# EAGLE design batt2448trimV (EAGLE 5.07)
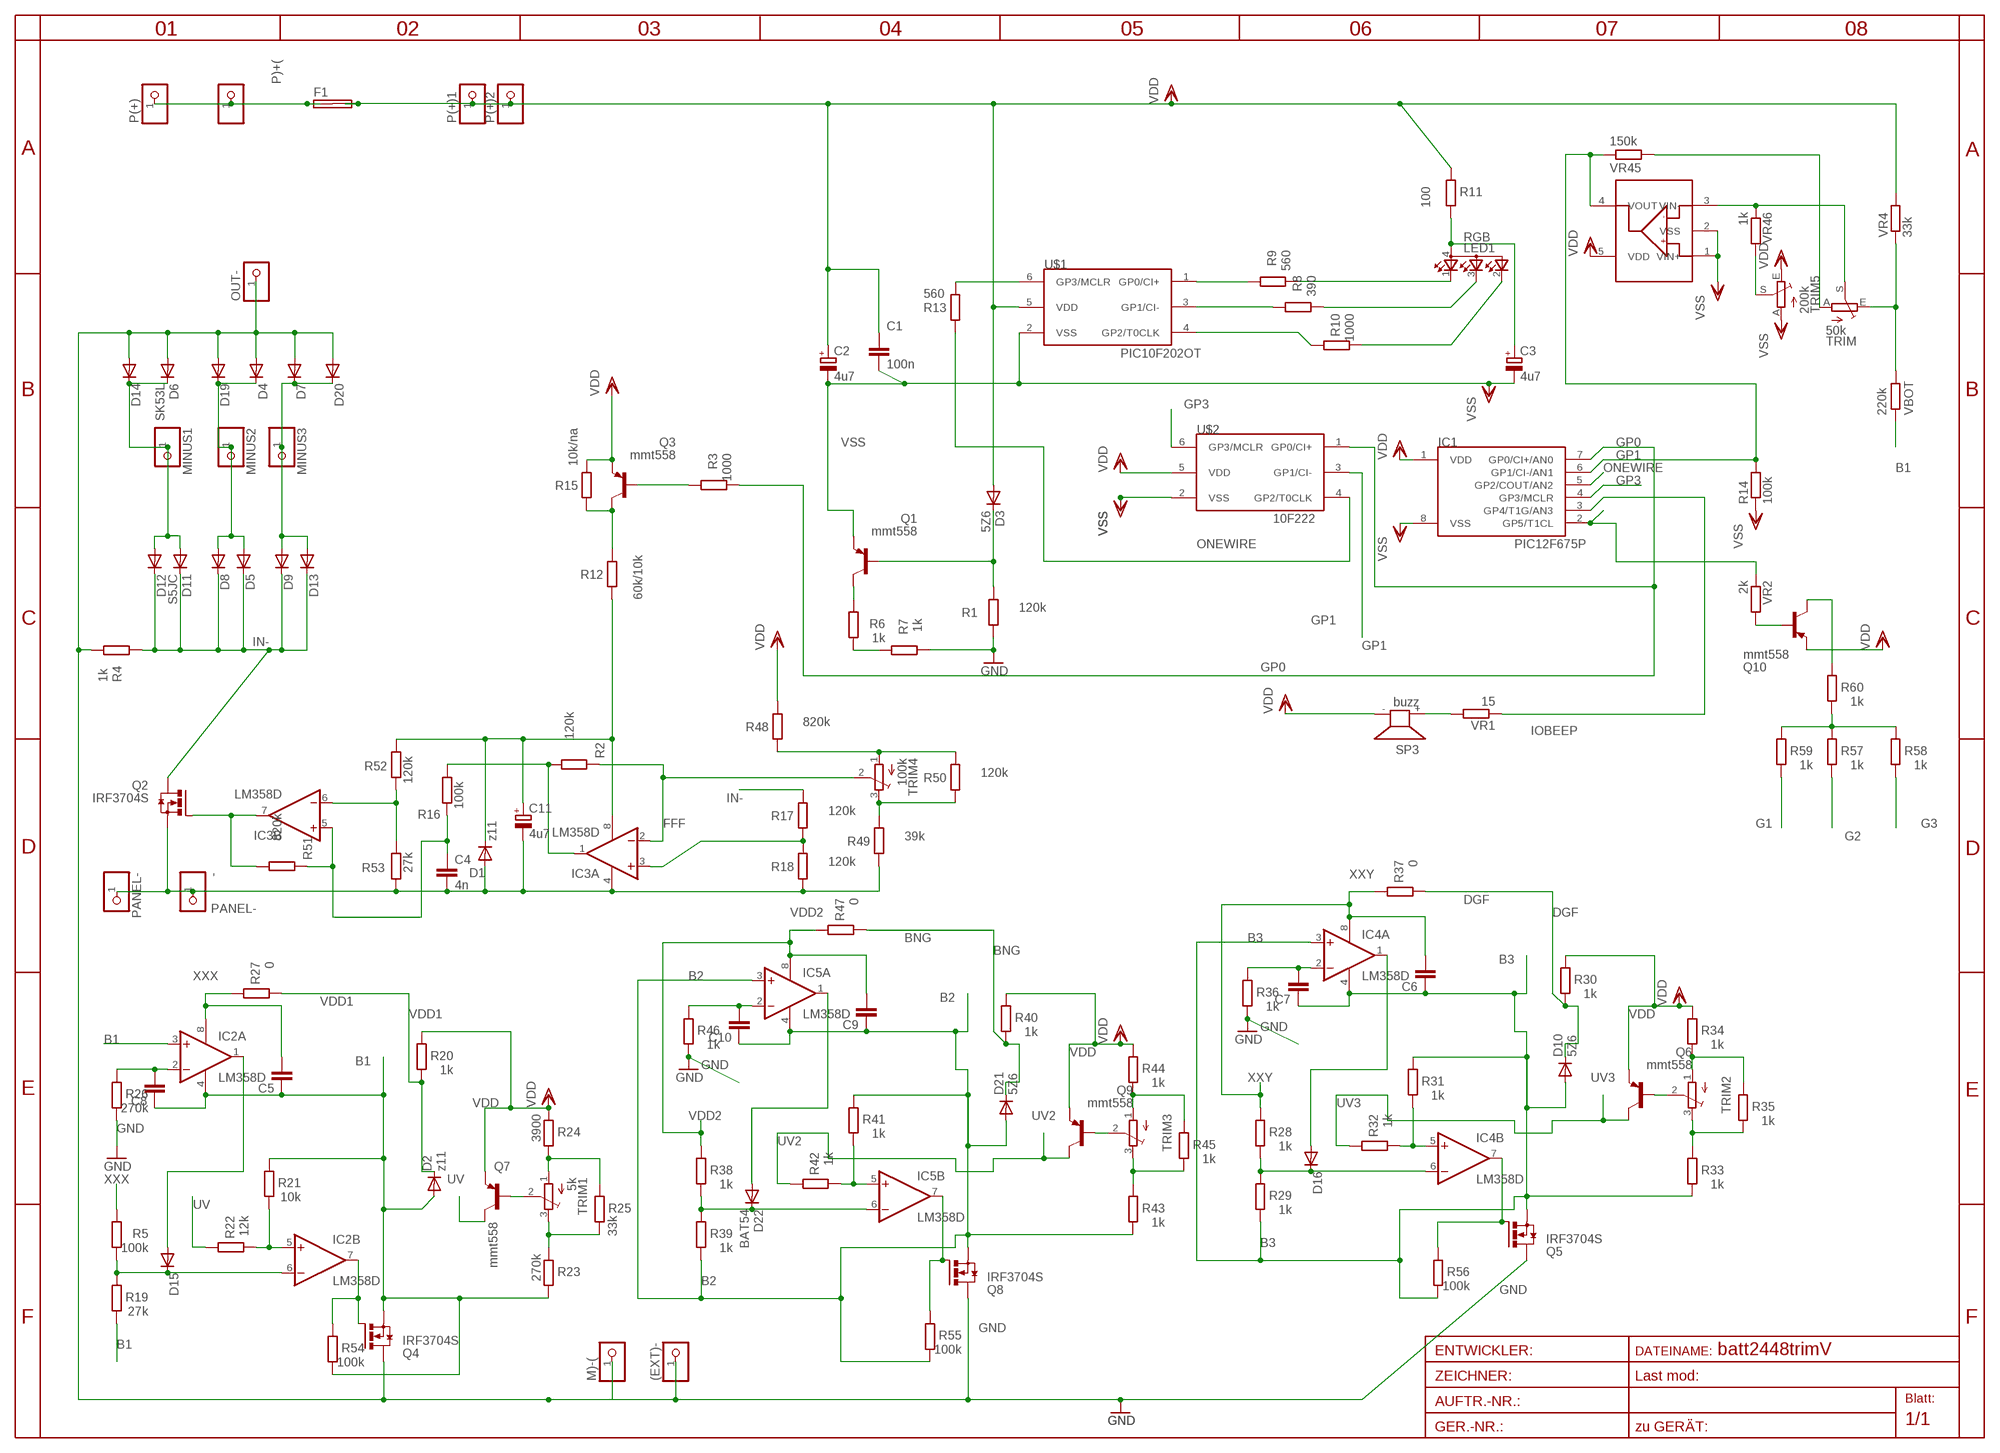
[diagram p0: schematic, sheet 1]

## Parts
(EXT)-  PINHD-1X11MM6  [1X1MM8]
-  PINHD-1X11MM6  [1X1MM8]
C1  100n  C-EUC1206  [C1206]
C2  4u7  CPOL-EUSMCA  [SMC_A]
C3  4u7  CPOL-EUSMCA  [SMC_A]
C4  4n  C-EUC0805  [C0805]
C5  C-EUC1206  [C1206]
C6  C-EUC1206  [C1206]
C7  C-EUC0805  [C0805]
C8  C-EUC0805  [C0805]
C9  C-EUC1206  [C1206]
C10  C-EUC0805  [C0805]
C11  4u7  CPOL-EUSANYO_SMD_B6  [SANYO-OSCON_SMD_B6]
D1  z11  DIODE-MINIMELF  [MINIMELF]
D2  z11  DIODE-MINIMELF  [MINIMELF]
D3  5Z6  DIODE-MINIMELF  [MINIMELF]
D4  DIODE-SMC  [SMC]
D5  DIODE-SMC  [SMC]
D6  SK53L  DIODE-SMC  [SMC]
D7  DIODE-SMC  [SMC]
D8  DIODE-SMC  [SMC]
D9  DIODE-SMC  [SMC]
D10  5Z6  DIODE-MINIMELF  [MINIMELF]
D11  S5JC  DIODE-SMC  [SMC]
D12  DIODE-SMC  [SMC]
D13  DIODE-SMC  [SMC]
D14  DIODE-SMC  [SMC]
D15  DIODE-MINIMELF  [MINIMELF]
D16  DIODE-MINIMELF  [MINIMELF]
D19  DIODE-SMC  [SMC]
D20  DIODE-SMC  [SMC]
D21  5Z6  DIODE-MINIMELF  [MINIMELF]
D22  BAT54  DIODE-MINIMELF  [MINIMELF]
F1  SHK20L7MM5  [7MM5]
IC1  PIC12F675P  [DIL8]
IC2  LM358D  [SO08]
IC3  LM358D  [SO08]
IC4  LM358D  [SO08]
IC5  LM358D  [SO08]
IC6  MCP6001U  [SOT23-5L]
LED1  RGB  GM1WA55311A  [FULL3528]
M)-(  PINHD-1X11MM6  [1X1MM8]
MINUS1  PINHD-1X12MM3  [1X2MM3]
MINUS2  PINHD-1X12MM3  [1X2MM3]
MINUS3  PINHD-1X12MM3  [1X2MM3]
OUT-  PINHD-1X12MM3  [1X2MM3]
P(+)  PINHD-1X12MM3  [1X2MM3]
P(+)1  PINHD-1X12MM3  [1X2MM3]
P(+)2  PINHD-1X13MM2  [1X3MM2]
P)+(  PINHD-1X11X0.4  [1X01]
PANEL-  PINHD-1X12MM3  [1X2MM3]
Q1  mmt558  BC857ALT1SMD  [SOT23-BEC]
Q2  IRF3704S  [D2PACK]
Q3  mmt558  BC857ALT1SMD  [SOT23-BEC]
Q4  IRF3704S  [D2PACK]
Q5  IRF3704S  [D2PACK]
Q6  mmt558  BC857ALT1SMD  [SOT23-BEC]
Q7  mmt558  BC857ALT1SMD  [SOT23-BEC]
Q8  IRF3704S  [D2PACK]
Q9  mmt558  BC857ALT1SMD  [SOT23-BEC]
Q10  mmt558  BC857ALT1SMD  [SOT23-BEC]
R1  120k  R-EU_R1206  [R1206]
R2  120k  R-EU_R0805  [R0805]
R3  1000  R-EU_R0805  [R0805]
R4  1k  R-EU_0207/25  [0207/25]
R5  100k  R-EU_R1206  [R1206]
R6  1k  R-EU_R1206  [R1206]
R7  1k  R-EU_R1206  [R1206]
R8  390  R-EU_R0805  [R0805]
R9  560  R-EU_R0805  [R0805]
R10  1000  R-EU_R0805  [R0805]
R11  100  R-EU_R1206  [R1206]
R12  60k/10k  R-EU_R1206  [R1206]
R13  560  R-EU_R0805  [R0805]
R14  100k  R-EU_R1206  [R1206]
R15  10k/na  R-EU_R0805  [R0805]
R16  100k  R-EU_R0805  [R0805]
R17  120k  R-EU_R0805  [R0805]
R18  120k  R-EU_R0805  [R0805]
R19  27k  R-EU_R0805  [R0805]
R20  1k  R-EU_R1206  [R1206]
R21  10k  R-EU_R0805  [R0805]
R22  12k  R-EU_R1206  [R1206]
R23  270k  R-EU_R0805  [R0805]
R24  3900  R-EU_R0805  [R0805]
R25  33k  R-EU_R0805  [R0805]
R26  270k  R-EU_R1206  [R1206]
R27  0  R-EU_R1203  [R1203]
R28  1k  R-EU_R1206  [R1206]
R29  1k  R-EU_R0805  [R0805]
R30  1k  R-EU_R1206  [R1206]
R31  1k  R-EU_R0805  [R0805]
R32  1k  R-EU_R1206  [R1206]
R33  1k  R-EU_R0805  [R0805]
R34  1k  R-EU_R0805  [R0805]
R35  1k  R-EU_R0805  [R0805]
R36  1k  R-EU_R1206  [R1206]
R37  0  R-EU_R1203  [R1203]
R38  1k  R-EU_R1206  [R1206]
R39  1k  R-EU_R0805  [R0805]
R40  1k  R-EU_R1206  [R1206]
R41  1k  R-EU_R0805  [R0805]
R42  1k  R-EU_R1206  [R1206]
R43  1k  R-EU_R0805  [R0805]
R44  1k  R-EU_R0805  [R0805]
R45  1k  R-EU_R0805  [R0805]
R46  1k  R-EU_R1206  [R1206]
R47  0  R-EU_R1203  [R1203]
R48  820k  R-EU_R0805  [R0805]
R49  39k  R-EU_R1206  [R1206]
R50  120k  R-EU_R0805  [R0805]
R51  820k  R-EU_R0805  [R0805]
R52  120k  R-EU_R1206  [R1206]
R53  27k  R-EU_R1206  [R1206]
R54  100k  R-EU_R0805  [R0805]
R55  100k  R-EU_R0805  [R0805]
R56  100k  R-EU_R0805  [R0805]
R57  1k  R-EU_0207-17MM5  [0207/17MM5]
R58  1k  R-EU_0207-17MM5  [0207/17MM5]
R59  1k  R-EU_0207/10  [0207/10]
R60  1k  R-EU_R0805  [R0805]
SP3  buzz  KSS12017MM  [KSS1202]
TRIM  50k  TRIM_EU-S64W  [S64W]
TRIM1  5k  TRIM_EU-3223G  [3223G]
TRIM2  TRIM_EU-3223G  [3223G]
TRIM3  TRIM_EU-3223G  [3223G]
TRIM4  100k  TRIM_EU-3223G  [3223G]
TRIM5  200k  TRIM_EU-S64W  [S64W]
U$1  PIC10F202OT  [SOT23-6]
U$2  10F222  PIC10F204OT  [SOT23-6]
VBOT  220k  R-EU_R0805  [R0805]
VR1  15  R-EU_R0805  [R0805]
VR2  2k  R-EU_R0805  [R0805]
VR4  33k  R-EU_R1206  [R1206]
VR45  150k  R-EU_R0805  [R0805]
VR46  1k  R-EU_R0805  [R0805]

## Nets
A: C3.+ LED1.4(A) R11.1
B: LED1.3(CBLUE) R8.1
B1: C5.1 C8.1 D2.A D6.C D11.A D12.A D14.C IC2.3(A:+IN) IC2.4(P:V-) MINUS1.1 Q4.3(S) R19.1 R21.2 R23.1 R54.1 VBOT.1
B2: C9.1 C10.1 D7.C D9.A D13.A D20.C D21.A IC5.3(A:+IN) IC5.4(P:V-) MINUS3.1 Q8.3(S) R39.1 R41.2 R43.1 R55.1
B3: C6.1 C7.1 D4.C D5.A D8.A D10.A D19.C IC4.3(A:+IN) IC4.4(P:V-) MINUS2.1 Q5.3(S) R29.1 R31.2 R33.1 R56.1
BNG: D21.C R40.1 R47.1
BUZZ+: SP3.+ VR1.2
DGF: D10.C R30.1 R37.1
DIGOUT: R57.2 R58.2 R59.2 R60.1
FFF: IC3.2(A:-IN) R2.2 TRIM4.2(S)
G: LED1.2(CGREEN) R10.1
G1: IC2.7(B:OUT) Q4.1(G) R54.2 R59.1
G2: IC5.7(B:OUT) Q8.1(G) R55.2 R57.1
G3: IC4.7(B:OUT) Q5.1(G) R56.2 R58.1
GND: (EXT)-.1 D4.A D6.A D7.A D14.A D19.A D20.A M)-(.1 OUT-.1 Q4.2(D) Q5.2(D) Q8.2(D) R1.2 R4.1 R7.1 R26.1 R36.1 R46.1
GP0: IC1.7(GP0/CI+/AN0) R3.1 U$2.1(GP0/CI+)
GP0C: R9.2 U$1.1(GP0/CI+)
GP1: IC1.6(GP1/CI-/AN1) IC6.4(VOUT) R14.2 U$2.3(GP1/CI-) VR45.1
GP1C: R8.2 U$1.3(GP1/CI-)
GP2C: R10.2 U$1.4(GP2/T0CLK)
GP3: IC1.4(GP3/MCLR) U$2.6(GP3/MCLR)
GP3_2: R13.1 U$1.6(GP3/MCLR)
IN+: F1.1A F1.1B P(+).1 P)+(.1
IN-: D5.C D8.C D9.C D11.C D12.C D13.C Q2.2(D) R4.2 R17.1
IOBEEP: IC1.3(GP4/T1G/AN3) VR1.1
N$1: D15.C IC2.6(B:-IN) R5.1 R19.2
N$2: D3.C Q1.B R1.1
N$4: C11.+ D1.C IC3.8(P:V+) R12.2 R52.1
N$5: TRIM.E VBOT.2 VR4.1
N$6: Q1.C R6.2
N$7: TRIM5.S VR46.2
N$8: Q3.B R3.2
N$9: Q10.B VR2.2
N$10: IC2.5(B:+IN) R21.1 R22.1
N$11: Q3.C R12.1 R15.2
N$12: TRIM.A VR45.2
N$13: IC3.1(A:OUT) R2.1 R16.1
N$14: IC6.3(VIN-) TRIM.S VR46.1
N$16: IC3.3(A:+IN)
N$17: D15.A IC2.1(A:OUT)
N$18: R6.1 R7.2
N$19: R17.2 R18.1
N$20: C8.2 IC2.2(A:-IN) R26.2
N$21: Q7.B TRIM1.2(S)
N$22: R24.1 R25.2 TRIM1.1(A)
N$23: R23.2 R25.1 TRIM1.3(E)
N$24: IC3.6(B:-IN) R52.2 R53.1
N$25: D16.C IC4.6(B:-IN) R28.1 R29.2
N$26: IC4.5(B:+IN) R31.1 R32.1
N$27: Q6.B TRIM2.2(S)
N$30: R34.1 R35.2 TRIM2.1(A)
N$31: R33.2 R35.1 TRIM2.3(E)
N$32: D16.A IC4.1(A:OUT)
N$33: C7.2 IC4.2(A:-IN) R36.2
N$34: Q10.C R60.2
N$35: D22.C IC5.6(B:-IN) R38.1 R39.2
N$36: IC5.5(B:+IN) R41.1 R42.1
N$37: Q9.B TRIM3.2(S)
N$38: IC1.2(GP5/T1CL) VR2.1
N$39: R44.1 R45.2 TRIM3.1(A)
N$40: R43.2 R45.1 TRIM3.3(E)
N$41: D22.A IC5.1(A:OUT)
N$42: C10.2 IC5.2(A:-IN) R46.2
N$43: R49.1 R50.2 TRIM4.3(E)
N$45: R48.2 R50.1 TRIM4.1(A)
N$46: C4.1 IC3.5(B:+IN) R16.2 R51.2
N$47: IC3.7(B:OUT) Q2.1(G) R51.1
ONEWIRE: IC1.5(GP2/COUT/AN2) R13.2 U$2.4(GP2/T0CLK)
PANEL-: -.1 C4.2 C11.- D1.A IC3.4(P:V-) PANEL-.1 Q2.3(S) R18.2 R49.2 R53.2
R: LED1.1(CRED) R9.1
UV: Q7.C R22.2
UV2: Q9.C R42.2
UV3: Q6.C R32.2
VDD: C1.1 C2.+ D3.A F1.2A F1.2B IC1.1(VDD) IC6.5(VDD) P(+)1.1 P(+)2.1 Q3.E Q6.E Q7.E Q9.E Q10.E R11.2 R15.1 R20.2 R24.2 R30.2 R34.2 R40.2 R44.2 R48.1 SP3.- TRIM5.E U$1.5(VDD) U$2.5(VDD) VR4.2
VDD1: D2.C R20.1 R27.1
VDD2: C9.2 IC5.8(P:V+) R38.2 R47.2
VSS: C1.2 C2.- C3.- IC1.8(VSS) IC6.1(VIN+) IC6.2(VSS) Q1.E R14.1 TRIM5.A U$1.2(VSS) U$2.2(VSS)
XXX: C5.2 IC2.8(P:V+) R5.2 R27.2
XXY: C6.2 IC4.8(P:V+) R28.2 R37.2

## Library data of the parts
(EXT)- - M)-( MINUS1-MINUS3 OUT- P(+) P(+)1 P(+)2 P)+( PANEL- = pinhead:PINHD-1X1: PIN HEADER
C1 C4-C10 = rcl:C-EU: CAPACITOR, European symbol
C2 C3 C11 = rcl:CPOL-EU: POLARIZED CAPACITOR, European symbol
D1-D16 D19-D22 = diode:DIODE-: DIODE
F1 = fuse:SHK20L: FUSE HOLDER 5 x 20 mm, SH contact, SHH1 Schukat, E1073 Buerklin
IC1 = microchip-3:PIC12F6*: uPC nW 1k Program Flash memory 2x Timer Comparator 10b A/D converter/ 4xIN
IC2-IC5 = linear:LM358: OP AMP also LM158; LM258; LM2904 Source: http://cache.national.com/ds/LM/LM158.pdf
IC6 = microchip-3:MCP6001U
LED1 = led:GM1WA55311A: Chip LED RGB Source: http://document.sharpsma.com/files/GM1WA55311A_SS.pdf
Q1 Q3 Q6 Q7 Q9 Q10 = transistor-pnp:BC857*: PNP Transistror
Q2 Q4 Q5 Q8 = transistor-power:IRF3704: SMPS MOSFET HEXFET® Power MOSFET Source: http://www.irf.com/product-info/datasheets/data/irf3704.pdf
R1-R13 R15-R21 R23-R26 R28-R36 R38-R46 R48-R60 VBOT VR1 VR2 VR4 VR45 VR46 = rcl-2:R-EU_: RESISTOR, European symbol
R14 R22 R27 R37 R47 = rcl:R-EU_: RESISTOR, European symbol
SP3 = buzzer:KSS1201: SPEAKER
TRIM TRIM1-TRIM5 = pot:TRIM_EU-: POTENTIOMETER
U$1 U$2 = microchip-3:PIC10F2*: uPC nW 0,25/0,5k Program Flash memory Comparator

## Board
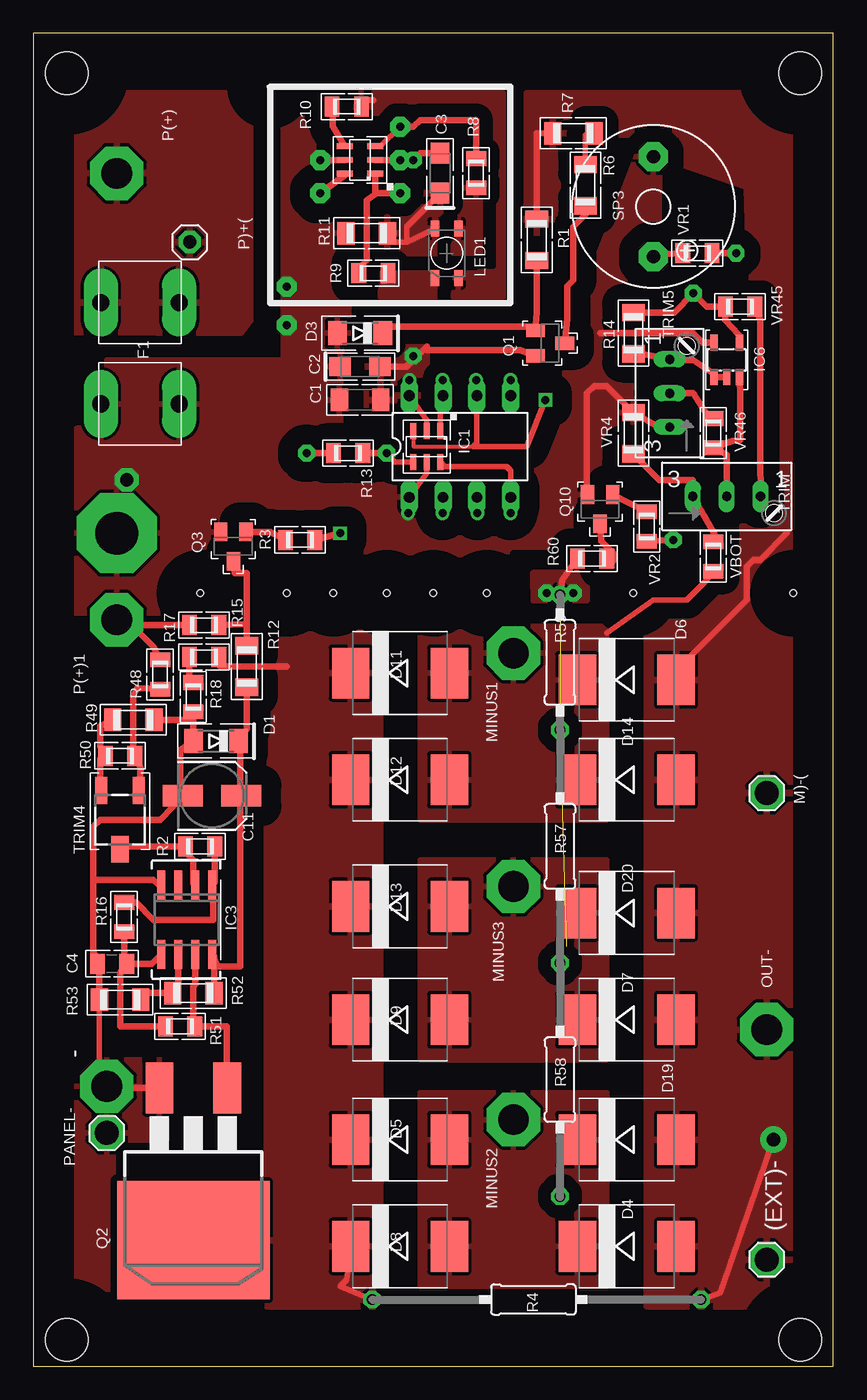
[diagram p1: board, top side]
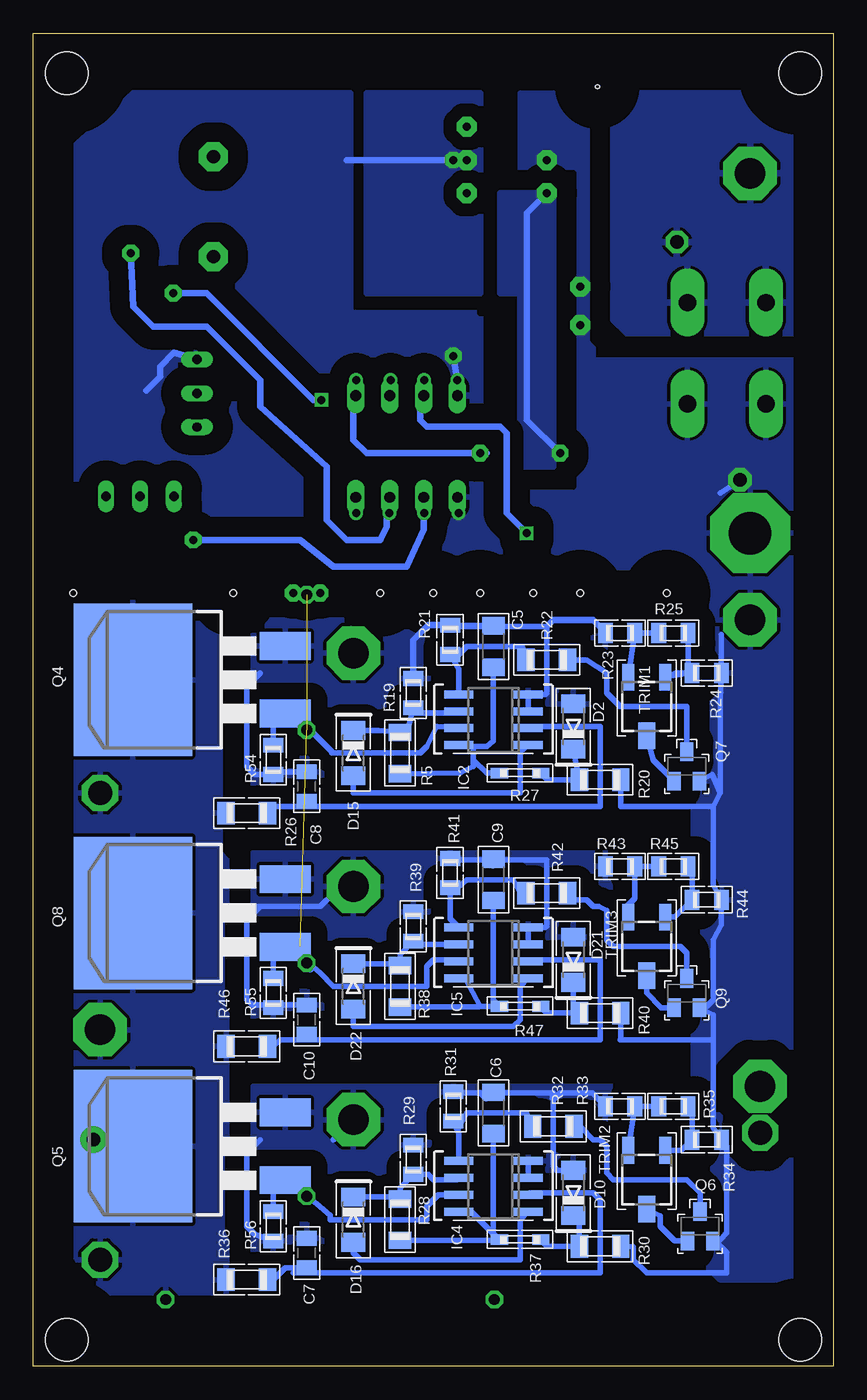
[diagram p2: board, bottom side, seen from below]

Size 60 x 100 mm. Coordinates in mm from the lower left corner, seen from the top.
Outline: 60,0 60,100 0,100 0,0 60,0
Copper layers (1*16): Top 0.035mm / dielectric 1.5mm / Bottom 0.035mm
Design rules "default *": minimum track width 8mil, minimum drill 0.3mm, track to track 8mil, track to pad 8mil, pad to pad 8mil, via to via 8mil, smd to smd 8mil, copper to edge 3mm, drill to drill 2mil, minimum pad ring 10mil, minimum via ring 8mil, stop-mask expansion 4mil, vias tented up to drill 0mil, thermal gap 10mil
Holes 3.2 mm at 2.5,2 57.5,2 2.5,97 57.5,97
Holes 0.5 mm at 34,58 30,58 26.5,58 22.5,58 45,58 57,58 19,58 12.5,58
Holes 0.3 mm at 17.7,96

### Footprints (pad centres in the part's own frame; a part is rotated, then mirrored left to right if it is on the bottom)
1X1MM8 = drill 1.8 pad 2.54 octagon: 1 0,0
C1206 = smd 1.3 x 1.7: 1 -1.55,0; 2 1.55,0
SMC_A = smd 1.6 x 1.4: + -1.5,0; - 1.5,0
C0805 = smd 1.1 x 1.5: 1 -1.1,0; 2 1.1,0
SANYO-OSCON_SMD_B6 = smd 3 x 1.6: + 2.2,0; - -2.2,0
MINIMELF = smd 1.4 x 1.8: A 1.7,0; C -1.7,0
SMC = smd 2.8 x 3.8: A 3.7,0; C -3.7,0
7MM5 = drill 1.3 pad 2.54 long: 1A -3.8,2.94; 1B -3.8,-2.94; 2A 3.8,2.94; 2B 3.8,-2.94
DIL8 = drill 0.813 long: 1 -3.81,-3.81; 2 -1.27,-3.81; 3 1.27,-3.81; 4 3.81,-3.81; 5 3.81,3.81; 6 1.27,3.81; 7 -1.27,3.81; 8 -3.81,3.81
SO08 = smd 0.6 x 2.2: 1 -1.905,-2.6; 2 -0.635,-2.6; 3 0.635,-2.6; 4 1.905,-2.6; 5 1.905,2.6; 6 0.635,2.6; 7 -0.635,2.6; 8 -1.905,2.6
SOT23-5L = smd 0.55 x 1.2: 1 -0.95,-1.3; 2 0,-1.3; 3 0.95,-1.3; 4 0.95,1.3; 5 -0.95,1.3
FULL3528 = smd 0.65 x 1.2: 1 0.875,1.85; 2 -0.875,1.85; 3 -0.875,-1.85; 4 0.875,-1.85
1X2MM3 = drill 2.3 pad 4 octagon: 1 0,0
1X3MM2 = drill 3.2 pad 6 octagon: 1 0,0
1X01 = drill 1 pad 1.676 octagon: 1 0,0
SOT23-BEC = smd 1 x 1.4: B -0.95,-1.1; C 0,1.1; E 0.95,-1.1
D2PACK = smd 2.083 x 3.81: 1 -2.54,-8.89; 3 2.54,-8.89 | smd 11.43 x 8.89: 2 0,2.54
R1206 = smd 1.3 x 1.7: 1 -1.55,0; 2 1.55,0
R0805 = smd 1.1 x 1.5: 1 -1.1,0; 2 1.1,0
0207/25 = drill 0.813 octagon: 1 -12.58,0; 2 12.08,0
R1203 = smd 1.3 x 0.8: 1 -1.55,0; 2 1.55,0
0207/17MM5 = drill 0.813 octagon: 1 -8.75,0; 2 8.75,0
0207/10 = drill 0.813 octagon: 1 -5.08,0; 2 5.08,0
KSS1202 = drill 1 pad 2.159 octagon: + 3.75,0; - -3.75,0
S64W = drill 0.7 long: A 2.54,1.27; E -2.54,1.27; S 0,1.27
3223G = smd 2 x 0.9: 1 -2.2,1.4; 3 -2.2,-1.4 | smd 2 x 1.3: 2 2.2,0
SOT23-6 = smd 0.45 x 1.2: 1 -1.016,-1.15; 2 0,-1.15; 3 1.016,-1.15; 4 1.016,1.15; 5 0,1.15; 6 -1.016,1.15

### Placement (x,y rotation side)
(EXT)-  55,8 90 top
-  5.5,17.5 90 top
C1  24.5,72.5 0 top
C2  24.5,75 0 top
C3  30.5,89.5 90 top
C4  5.9,30.2 180 top
C5  25.5,54 270 bottom
C6  25.5,19 270 bottom
C7  39.5,8.5 270 bottom
C8  39.5,43.5 270 bottom
C9  25.5,36.5 270 bottom
C10  39.5,26 270 bottom
C11  13.4,42.8 0 top
D1  13.7,46.9 180 top
D2  19.5,48 90 bottom
D3  24.5,77.5 180 top
D4  44.5,9 0 top
D5  27.5,17 0 top
D6  44.5,51.5 0 top
D7  44.5,26 0 top
D8  27.5,9 0 top
D9  27.5,26 0 top
D10  19.5,13 90 bottom
D11  27.5,52 0 top
D12  27.5,44 0 top
D13  27.5,34.5 0 top
D14  44.5,44 0 top
D15  36,46 270 bottom
D16  36,11 270 bottom
D19  44.5,17 0 top
D20  44.5,34 0 top
D21  19.5,30.5 90 bottom
D22  36,28.5 270 bottom
F1  8,76 270 top
IC1  32,69 0 top
IC2  25.5,48.5 90 bottom
IC3  11.5,33.5 180 top
IC4  25.5,13.5 90 bottom
IC5  25.5,31 90 bottom
IC6  52,75.5 0 top
LED1  31,83.5 180 top
M)-(  55,43 90 top
MINUS1  36,53.5 270 top
MINUS2  36,18.5 270 top
MINUS3  36,36 270 top
OUT-  55,25.25 270 top
P(+)  6.25,89.5 90 top
P(+)1  6.25,56 90 top
P(+)2  6.25,62.5 90 top
P)+(  11.73,84.34 90 top
PANEL-  5.5,21 270 top
Q1  38.75,76.75 270 top
Q2  12,12 180 top
Q3  15,61.5 180 top
Q4  50,51.5 90 bottom
Q5  50,16.5 90 bottom
Q6  10,10.5 0 bottom
Q7  11,45 0 bottom
Q8  50,34 90 bottom
Q9  11,28 0 bottom
Q10  42.5,64.3 180 top
R1  37.75,84.5 90 top
R2  12.5,39 180 top
R3  20,62 180 top
R4  37.5,5 180 top
R5  32.5,46 270 bottom
R6  41.4,88.6 270 top
R7  40.5,92.5 0 top
R8  33.2,89.5 90 top
R9  25.5,82 180 top
R10  23.5,94.5 180 top
R11  25,85 180 top
R12  16,52.5 270 top
R13  23.6,68.5 0 top
R14  45,77.5 90 top
R15  12.8,55.6 0 top
R16  6.8,33.7 270 top
R17  12.8,53.2 180 top
R18  12,50.2 270 top
R19  31.5,50.5 270 bottom
R20  17.5,44 0 bottom
R21  28.75,54.5 90 bottom
R22  21.5,53 0 bottom
R23  16,55 0 bottom
R24  9.5,52 0 bottom
R25  12,55 0 bottom
R26  44,41.5 0 bottom
R27  23.5,44.5 180 bottom
R28  32.5,11 270 bottom
R29  31.5,15.5 270 bottom
R30  17.5,9 0 bottom
R31  28.5,19.5 90 bottom
R32  21,18 0 bottom
R33  16,19.5 0 bottom
R34  9.5,17 0 bottom
R35  12,19.5 0 bottom
R36  44,6.5 0 bottom
R37  23.5,9.5 180 bottom
R38  32.5,28.5 270 bottom
R39  31.5,33 270 bottom
R40  17.5,26.5 0 bottom
R41  28.75,37 90 bottom
R42  21.5,35.5 0 bottom
R43  16,37.5 0 bottom
R44  9.5,35 0 bottom
R45  12,37.5 0 bottom
R46  44,24 0 bottom
R47  23.5,27 180 bottom
R48  9.5,51.9 270 top
R49  7.5,48.5 0 top
R50  6.5,45.8 180 top
R51  11,25.5 180 top
R52  12,28 180 top
R53  6.5,27.5 180 top
R54  42,45.5 90 bottom
R55  42,28 90 bottom
R56  42,10.5 90 bottom
R57  39.5,39 90 top
R58  39.5,21.5 90 top
R59  39.5,52.8 90 top
R60  41.9,60.6 0 top
SP3  46.5,87 270 top
TRIM  52,64 0 top
TRIM1  14,49.5 270 bottom
TRIM2  14,14 270 bottom
TRIM3  14,31.5 270 bottom
TRIM4  6.5,41 270 top
TRIM5  49,73 90 top
U$1  24.5,90.5 90 top
U$2  29.5,69 180 top
VBOT  51,60.75 90 top
VR1  49.8,83.5 180 top
VR2  46,63 90 top
VR4  45,70 90 top
VR45  53,79.5 0 top
VR46  51,70 90 top

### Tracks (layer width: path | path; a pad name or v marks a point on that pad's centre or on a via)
A
  Top 0.4: 28,84.35 26.7,84.35 R11.1 | 28,84.35 LED1.4 | C3.+ 28,85.5 28,84.35
  pour Top (isolate 1, rank 2): 26,83.5 26,88.5 30.5,88.5 30.5,83.5
B
  pour Top (isolate 1.016): 31.5,83.5 31.5,85 32,85.5 32,89.5 33.5,89.5 33.5,83.5
B1
  Top 0.406: VBOT.1 50.5,59 49,57.5 46.5,57.5 43,55
  Bottom 0.406: IC2.3 IC2.4 21.59,50.41 21.5,50.5 21.5,55.5 25.05,55.5 C5.1 | 43,52 44,51 44,45 43.4,44.4 R54.1 41.2,44.6 C8.1
  Bottom 0.5: R23.1 17.1,55.1 18,56 21,56 21.5,55.5 | C5.1 28.7,55.55 R21.2 30.4,55.6 31.5,54.5 R19.1
  pour Top (isolate 1, rank 2): 43,55.5 43,41 29,41 29,55.5
  pour Bottom (isolate 1.25, rank 4): 43.5,56 43.5,41.5 16.5,41.5 16.5,56
B2
  Bottom 0.406: IC5.3 IC5.4 21.59,32.91 21.5,33 21.5,38 25.05,38 C9.1 25.55,37.55 26,38 28.35,38 R41.2 | 43,34.5 43.5,34.5 | 43,34.5 38.5,34.5 38,35 MINUS3.1 | C10.1 41.7,27.1 | 41.7,27.1 R55.1 | 41.7,27.1 43.6,27.1 44,27.5 44,33.5 43,34.5
  pour Top (isolate 1, rank 3): 43,23 29,23 29,38 43,38
  pour Bottom (isolate 1.25, rank 3): 43.5,23 16.5,23 16.5,38.5 43.5,38.5
B3
  Bottom 0.406: D10.A 20.7,14.7 21,15 21,20 | 21,20 20.5,20.5 18.1,20.5 R33.1 | 37.5,17 MINUS2.1 | IC4.3 IC4.4 | 21,20 21.1,20.1 21.1,20.4 21,20.5 25.05,20.5 C6.1 26.05,20.05 26.5,20.5 28.1,20.5 R31.2 | R56.1 43.4,9.9 44,10.5 44,16 43,17
  pour Top (isolate 1, rank 4): 43,6 29,6 29,20.5 43,20.5
  pour Bottom (isolate 1.25, rank 4): 43.5,5.5 16.5,5.5 16.5,21 43.5,21
BNG
  Bottom 0.406: R47.1 21.95,26.95 21.5,26.5 R40.1 19.5,26.95 D21.C
BUZZ+
  Top 0.5: VR1.2 46.64,83.39 SP3.+
DGF
  Bottom 0.406: R37.1 21.45,9 R30.1 19.05,10.85 D10.C
DIGOUT  (via drill 0.6 pad 1.27)  (2 unrouted)
  Top 0.5: R60.1 39.65,59 R59.2
  Bottom 0.406: R58.2 39.5,31 40,31.5
  other vias: 40.5,58 38.5,58
  pour Top (isolate 1.5): 37.5,57.5 37.5,59.5 42,59.5 42,58 41.5,57.5
FFF
  Top 0.5: TRIM4.2 7.2,39 R2.2 11.4,38.6 12,38 12,36.23 IC3.2
G
  Top 0.5: R10.1 24.6,95 25.5,95
  pour Top (isolate 1, rank 2): 31.5,80.25 31.5,82 33.5,82 33.5,94 24,94 24,95.5 35.25,95.5 35.25,80.25
G1
  Bottom 0.406: IC2.7 29.73,48 30.5,46.5 31,46 37.61,46 37.61,46.11 39,47.5 39.15,47.5 R59.1 | R54.2 42,48.46 Q4.1
  Bottom 0.5: Q4.1 40.74,48.96 R59.1
G2
  Bottom 0.406: IC5.7 28.36,30.36 28.5,30.5 30,30.5 30.5,30 30.5,28.5 37.5,28.5 38.5,29.5 39.02,29.97 | 39.02,29.97 40,30.85 Q8.1 42,30.57 R55.2 | R57.1 39.25,29.75 39.02,29.97
G3
  Bottom 0.406: IC4.7 29.64,12.87 30.5,12 30.5,11 37.75,11 37.75,11.32 38.75,12.2 R58.1 39.5,13.5 40,14 41.07,14 Q5.1 42,13.07 R56.2
GND  (via drill 1 pad 2)
  Top 0.406: v55.5,17 51.5,5.5 R4.1 | 37.75,92.5 R7.1
  Top 0.5: R1.2 37.75,92.5 | D6.A 48.2,52.2 53.5,57.5 53.5,60 54,60.5 54.5,60.5 56.5,62.5
  pour Top (isolate 1.2, rank 5): 58,95.5 58,9.8 54.5,4.5 46,4.5 46,71.5 54,71.5 53.5,88.5 40.5,93 40.5,85 37,85 37,95.5
  pour Bottom (isolate 1.422, rank 4): 57.5,57.3 58,9.8 55,5.5 45.5,5.5 45.5,38 46,38.5 46,57.3
GP0  (via drill 0.6, 0.6 pad 1)
  Top 0.4: U$2.1 30.52,72.6 IC1.7
  Top 0.406: v30.7,74 30.7,72.84 IC1.7
  Top 0.5: R3.1 v23,62.5
  Bottom 0.5: v30.7,74 30.5,74.2 | v23,62.5 24.5,64 24.5,70 25,70.5 30.5,70.5 31,71 31,72.54 IC1.7
GP0C  (via drill 0.6 pad 1.5)
  Top 0.4: R9.2 24.4,82.4 25,83
  Top 0.5: 25.75,88 v27.5,88 | 25,83 25,87.47 25.75,88 | U$1.1 25.65,88.1 25.75,88
GP1  (via drill 0.6, 0.6 pad 1, 0.6 pad 1.27)
  Top 0.3: 33,69 28.5,69 28.5,70.13
  Top 0.4: IC1.6 33.27,69.27 33,69 37,69 v38.4,72.5
  Top 0.406: IC1.6 33.27,73.93 v33.2,74 | U$2.3 28.5,70.13
  Top 0.5: IC6.4 52.95,76.55 52.9,77.4 51.9,78.5 VR45.1 50.5,79.5 v49.5,80.5 48.05,79.05 R14.2 45.05,79
  Bottom 0.5: v49.5,80.5 47,80.5 39,72.5 v38.4,72.5
GP1C  (via drill 0.6 pad 1.5)
  Top 0.4: U$1.3 26.02,91.52 v27.5,93
  Top 0.5: v27.5,93 28.5,93 29,93.5 33.2,93.5 R8.2
GP2C
  Top 0.5: U$1.4 22.45,93.05 22.45,94.5 R10.2
GP3  (via drill 0.6 pad 1)
  Top 0.4: IC1.4 35.81,67.19 35.5,67.5 30.87,67.5 U$2.6
  Top 0.406: IC1.4 v35.81,64.01 v35.8,64
GP3_2  (via drill 0.6 pad 1.27, 0.6 pad 1.5)
  Top 0.5: U$1.6 23.35,89.35 v21.5,88 | R13.1 v20.5,68.5
  Bottom 0.5: v21.5,88 23,86.5 23,71 v20.5,68.5
  pour Bottom (isolate 1): 21,67.5 21,88 25,88 25,80.5 23.5,80.5 23.5,67.5
IN+
  pour Top (isolate 1.5): 3,77.6 3,95.5 16.25,95.5 16.25,78.5 15.5,77.5
  pour Bottom (isolate 1.5): 3,77.5 3,95.5 16.5,95.5 16.5,78.5 15.5,77.5
IN-
  Top 0.406: R4.2 23,6 23.5,6.5 D8.C
  Top 0.5: R17.1 14,52.5 19,52.5
  pour Top (isolate 1.5): 17.5,4.5 17.5,55.5 26,55.5 26,4.5
IOBEEP  (via drill 0.6 pad 1, 0.6 pad 1.27)
  Top 0.5: VR1.1 51.89,83.51 v52.7,83.5
  Bottom 0.406: 33.5,64.96 IC1.3
  Bottom 0.5: 33.5,64.96 33.5,64 v33.3,64 33.5,63.8 33.5,63 34,62 36.5,62 38,63.5 38,67.5 43,72 43,74 47,78 51,78 52.5,79.5 v52.7,83.5
N$1
  Bottom 0.406: D15.C 34.15,47.7 R5.1 31.85,48.05 R19.2 31.5,49 28.23,49 IC2.6
N$2
  Top 0.5: D3.C 26.21,77.72 26.5,78 37.35,78 Q1.B 37.75,79.1 R1.1
N$3  (via drill 0.6 pad 1)
  other vias: 35.8,74
N$4
  Top 0.5: R52.1 13.55,30.75 IC3.8 13.8,30 15.5,30 15.5,42.9 | R12.2 16,47.8 D1.C 15,46.5 15.5,46 15.5,43 | 15.5,42.9 15.5,43 | 15.5,42.9 C11.+ 15.6,42.9 15.5,43
N$5
  Top 0.5: VBOT.2 51.05,62.46 TRIM.E 49.46,66.5 46.95,66.5 VR4.1
N$6
  Top 0.5: R6.2 41.5,86.5 40.5,85.5 40.5,81.5 40.05,81.05 40.05,78.55 Q1.C
N$7
  Top 0.5: VR46.2 50.4,71.6 49.5,73 TRIM5.S
N$8
  Top 0.5: Q3.B 17.8,62.6 R3.2
N$9
  Top 0.5: Q10.B VR2.2
N$10
  Bottom 0.406: IC2.5 28.1,52.3 R21.1 28.1,53.4 27.5,54 23.35,54 R22.1
N$11
  Top 0.5: R15.2 16,55.7 | 16,55.7 R12.1 | 16,55.7 16,59.5 15.1,59.5 Q3.C
N$12
  Top 0.5: VR45.2 54.5,78.5 54.5,68.23 TRIM.A
N$13
  Top 0.5: R16.1 7.7,34.8 9,33.5 13.5,33.5 13.5,35.51 IC3.1 13.6,36.3 R2.1
N$14
  Top 0.5: TRIM.S 52,68.4 VR46.1 52.4,69.4 53,69.5 53,73.15 IC6.3
N$17
  Bottom 0.406: D15.A 36,43 23.5,43 23.5,46.09 IC2.1
N$18
  Top 0.406: R6.1 41.4,92.35 R7.2
N$19
  Top 0.5: R18.1 12,51.5 11.7,51.5 R17.2
N$20
  Bottom 0.406: 42.45,42 R26.2 | 39.5,42 42.45,42 | 39.5,42 17.5,42 17.5,48 22.9,48 IC2.2 | 42.45,42 42.4,42.05 | 39.5,42 C8.2
N$21
  Bottom 0.406: Q7.B 13.5,45.5 TRIM1.2
N$22
  Bottom 0.406: 10.9,52 R25.2 | 10.9,52 TRIM1.1 11.8,52 10.9,52 | 10.9,52 R24.1
N$23
  Bottom 0.406: R25.1 R23.2 TRIM1.3
N$24
  Top 0.5: R53.1 8.55,28 R52.2 10.87,28.41 IC3.6
N$25
  Bottom 0.406: D16.C 32.65,12.7 R28.1 32.5,13.4 R29.2 30.4,14.4 30,14 28.23,14 IC4.6
N$26
  Bottom 0.406: IC4.5 28.1,17.5 R31.1 28.1,17.9 27.5,19 23.05,19 R32.1
N$27
  Bottom 0.406: Q6.B 11.9,9.4 13,10.5 13,11.3 TRIM2.2
N$29  (via drill 0.6 pad 1)
  other vias: 30.7,64
N$30
  Bottom 0.406: R35.2 10.6,19.2 R34.1 11.4,16.2 TRIM2.1
N$31
  Bottom 0.406: R35.1 R33.2 TRIM2.3
N$32
  Bottom 0.406: IC4.1 23.5,11 23.5,8 35.5,8 36,8.5 D16.A
N$33
  Bottom 0.406: 40,7 40.5,7 | 40,7 17.5,7 17.5,12.5 18,13 22.77,13 IC4.2 | 40.4,7.4 C7.2 | R36.2 42,6.5 41.1,7.4 40.4,7.4 | 40,7 40.4,7.4
N$34
  Top 0.5: Q10.C 42.6,61.9 43.5,61 43.5,60.4 R60.2
N$35
  Bottom 0.406: D22.C 32.65,30.2 R38.1 32.5,30.9 R39.2 31.23,31.64 IC5.6
N$36
  Bottom 0.406: R42.1 23.5,35.5 24,36.5 27.5,36.5 28.65,35.5 R41.1 28.75,33.55 IC5.5
N$37
  Bottom 0.406: Q9.B 12.9,26.9 14,28 TRIM3.2
N$38  (via drill 0.6 pad 1.27)
  Top 0.5: v48,62 VR2.1
  Bottom 0.5: IC1.2 30.73,62.77 32,60 37.5,60 40,62 v48,62
N$39
  Bottom 0.406: TRIM3.1 11.9,33.7 R44.1 10.6,37.2 R45.2
N$40
  Bottom 0.406: R45.1 R43.2 14.9,35.1 15.5,34.5 15.5,33.8 TRIM3.3
N$41
  Bottom 0.406: D22.A 36,25.5 24,25.5 23.5,26 23.5,28.5 IC5.1
N$42
  Bottom 0.406: 39.5,24.5 41.5,24.5 42,24 R46.2 | 39.5,24.5 17.5,24.5 17.5,30.5 22.77,30.5 IC5.2 | 39.5,24.5 C10.2
N$43
  Top 0.5: TRIM4.3 5.1,43.4 5,44 5,45.55 R50.2 5.45,46.05 5,46.5 5,48.05 R49.1
N$45
  Top 0.5: R48.2 7.8,50.9 7.5,50.3 7.5,46.55 R50.1 8.05,44.85 TRIM4.1
N$46
  Top 0.5: R51.2 6.5,25.5 6.5,29.5 C4.1 | C4.1 8.89,30.2 IC3.5 | R16.2 6.8,30.6 C4.1
N$47
  Top 0.5: IC3.7 12.13,28.64 12,28.5 12,25.6 R51.1 14.5,25.5 14.5,21 14.54,20.96 Q2.1
ONEWIRE  (via drill 0.6 pad 1.27)
  Top 0.4: 27.5,67.85 U$2.4
  Top 0.406: v26.5,68.5 27.15,67.85 27.5,67.85
  Top 0.5: R13.2 v26.5,68.5
  Bottom 0.406: v26.5,68.5 26,68.5 | 36,72.62 IC1.5
  Bottom 0.5: 36,72.62 36,69.5 35,68.5 26,68.5
PANEL-
  Top 0.406: R53.2 4.95,21.94 6,20.89
  Top 0.5: 4.5,36.5 4.5,40.5 5,41 9.5,41 10.5,42 10.5,42.1 C11.- 11.2,42.7 11,42.5 11,46.2 D1.A | 4.5,36.5 4.5,31 4.8,30.7 C4.2 4.95,30.15 R53.2 | IC3.4 9.4,36.1 9,36.5 4.5,36.5 | D1.A 11.5,46.3 | D1.A R18.2 11.9,48.5 R49.2 | Q2.3 6,20.89 5.11,20.89 PANEL-.1
  pour Top (isolate 0.5): 2.5,5 2.5,23 10,23 10,17 6,17 6,5
R
  pour Top (isolate 1, rank 3, no thermals): 26,80.25 26,82 30.5,82 30.5,80.25
UV
  Bottom 0.406: Q7.C 11,49.5 16,49.5 17,50.5 17,52 18.5,53 R22.2 19.75,53
UV2
  Bottom 0.406: Q9.C 11,31 11.5,31.5 16.5,31.5 17,32 17,34.2 17.6,34.5 18,34.5 18.5,35 19.45,35 R42.2
UV3
  Bottom 0.406: Q6.C 10,13 11,14 16.5,14 17,14.5 17,16.5 17.5,17 18,17 19,18 R32.2 19.75,18
VDD  (via drill 0.6 pad 1, 0.6 pad 1.5, 1 pad 1.78)
  Top 0.4: U$2.5 29.5,67 IC1.1 28,65
  Top 0.406: SP3.- 45.75,90.75
  Top 0.5: v21.5,90.5 U$1.5 | R48.1 9,54 7,56 P(+)1.1 | P(+)1.1 6,56 | TRIM5.E 46.71,70.56 VR4.2 43,73.55 42.05,73.55 41.5,73 41.5,65.5 | IC6.5 50.2,76.8 49.5,77.5 42.5,77.5 | 28,65 28,64.1 v28.1,64 | R15.1 6.25,55.6 P(+)1.1
  Bottom 0.406: R20.2 15.95,42 9,42 | 9,42 8.5,43 | 8.5,43 8.5,49.9 R24.2 8.4,54.9 | Q7.E 9.1,44.4 8.5,43 | v7,66.5 8.5,65.5 | R30.2 15,8.95 15,8 14,7 8,7 8,8.5 8.9,9.4 Q6.E 8.95,9.5 8.5,9.5 8,10 8,16.5 8.4,16.9 R34.2 9,17.9 9,24.5 | R40.2 15.95,24.55 16,24.5 9,24.5 | 9,24.5 9,26.35 Q9.E 9.95,27 9.5,27 9,27.5 9,32 8.4,33.1 R44.2 9,36.1 9,42
  other vias: 19,78.1 19,81
  pour Top (isolate 1.5, rank 3): 18.75,75.5 5.5,75.5 5.5,71.5 2.5,70 2.5,56.5 9.5,56.5 9.5,59.5 46.5,59.5 47,91.5 45.5,91.5 35.5,65.5 28,66 27.5,66.5 23,70.5 23.5,71.5 24,95.5 18.75,95.5
  pour Bottom (isolate 1.5, rank 2): 18,75.5 2.5,75.5 3,59.5 3,6.5 8.5,6.5 10.5,8.5 10.5,58.5 12,60 30,59.5 30,66 28,66 27.5,66.5 23,70.5 23.5,71.5 23.5,95.5 18,95.5
VDD1
  Bottom 0.406: D2.C R20.1 21.45,44 R27.1
VDD2
  Bottom 0.406: R38.2 26.6,26.95 R47.2 | IC5.8 27.59,29.09 26.5,27 R47.2 | C9.2 25.5,27.45 R47.2
VSS  (via drill 0.6 pad 1, 0.6 pad 1.27, 0.6 pad 1.5)
  Top 0.4: U$2.2 29.5,71
  Top 0.406: 29.5,71 IC1.8
  Top 0.5: U$1.2 v27.5,90.5 | Q1.E 36.5,76.25 29.5,76.25 29.5,76.5 28,75 | C2.- 28,75 | 28,75 v28.5,75.8 | IC6.2 IC6.1 51.05,74.45 49.5,75.5 48.27,75.5 TRIM5.A 45.09,76.04 R14.1 | C3.- 29,91 v28.5,90.5
  Bottom 0.5: v27.5,90.5 36.5,90.5 | TRIM5.A 49.46,76.04 50.5,75 50.5,74.25 51.55,73.2 | v28.5,75.8 v28.2,74
  pour Bottom (isolate 1.5, rank 5): 26.5,72 26.5,79 36.25,79 36.25,95.5 52.5,95.5 57.5,91 57.5,61 53,59.5 39,59.5 39,72.5 36.5,75 31,75 31,72.5 30.5,72
  pour Top (isolate 1): 25,72 25,77 29.5,77 29.5,72
  pour Bottom (isolate 1, rank 5): 26.5,80.5 26.5,95.5 35,95.5 35,80.5
XXX
  Bottom 0.406: C5.2 25.5,46.9 26,46.5 27,46.5 | 27,46.5 28,46.5 IC2.8 | R5.2 28,44.5 27,45 27,45.5 | 27,45.5 27,46.5 | R27.2 26,44.5 27,45.5
XXY
  Bottom 0.406: C6.2 25.5,9.95 R37.2 | R28.2 25.1,9.45 R37.2 | IC4.8 27.14,11.6 R37.2

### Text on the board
tTest: 4v4
Document: 300u | 500u | 10u | 2mA | 5m | 5m | 10u | 5m | 300u | 5m | 300u | 5m | 5m | 5m | 1m | 1m | 30u | 12m | 500u | 14m | 2m | 40m | 40m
